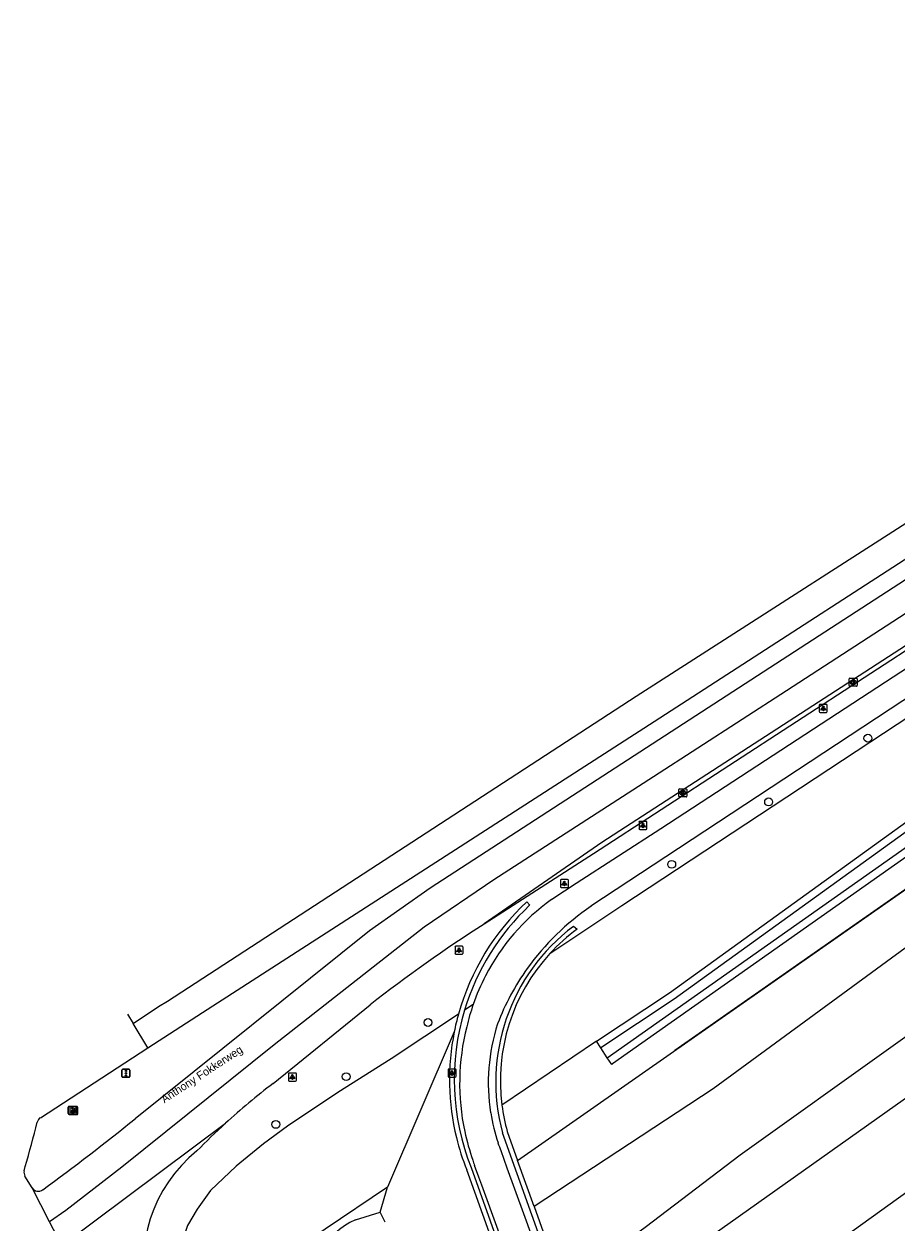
# Model space of a CAD drawing. Extents: x 156502 to 159074, y 384229 to 386094.
# Drawn here: x 156577.6 to 156686.5, y 385670.7 to 385820.5 of the extents above; entities that cross this region are included whole.
import ezdxf

# ---------------------------------------------------------------- set-up
doc = ezdxf.new("R2010")
doc.units = 0
for name, color, linetype in [('IMGEO_Berm_groen', 7, 'Continuous'), ('IMGEO_Boom', 7, 'Continuous'), ('IMGEO_Fietspad_gesloten', 7, 'Continuous'), ('IMGEO_Groenvoorziening', 7, 'Continuous'), ('IMGEO_Haag', 7, 'Continuous'), ('IMGEO_Hek', 7, 'Continuous'), ('IMGEO_Kolk', 7, 'Continuous'), ('IMGEO_Lichtpunt', 7, 'Continuous'), ('IMGEO_Loofbos', 7, 'Continuous'), ('IMGEO_Openbare_ruimte_label', 7, 'Continuous'), ('IMGEO_Rijbaan_regionaal_gesloten', 7, 'Continuous'), ('IMGEO_Rijbaan_regionaal_open', 7, 'Continuous'), ('IMGEO_Verkeersregelinstallatiepaal', 7, 'Continuous'), ('IMGEO_Waterloop', 7, 'Continuous')]:
    doc.layers.add(name, color=color, linetype=linetype)

msp = doc.modelspace()

# ---------------------------------------------------------------- linework, layer by layer
at = {"layer": 'IMGEO_Berm_groen'}
for points in [[(156633.7, 385697.92), (156632.64, 385697.21)], [(156631.87, 385696.71), (156623.47, 385691.12), (156616.78, 385686.91), (156610.49, 385682.74), (156607.53, 385680.53), (156604.1, 385677.72), (156600.9, 385674.67), (156599.21, 385672.33), (156598, 385670.31), (156597.11, 385667.59), (156596.91, 385665.45), (156597.24, 385662.91), (156597.95, 385660.68), (156598.83, 385658.73), (156598.95, 385658.46)], [(156623.02, 385675.08), (156615.23, 385669.86), (156612.01, 385667.6), (156610.4, 385666.16), (156609.58, 385664.78), (156609.43, 385663.6)], [(156622.07, 385671.98), (156623.02, 385675.08)], [(156618.99, 385671.01), (156622.07, 385671.98)]]:
    msp.add_lwpolyline(points, dxfattribs=at)
msp.add_arc((156622.65, 385662.64), 9.14, 113.6111, 190.3391, dxfattribs=at)
at = {"layer": 'IMGEO_Boom'}
for centre in [(156683.03, 385731.21), (156670.62, 385723.25), (156658.52, 385715.44), (156628.07, 385695.68), (156617.84, 385688.91), (156609.05, 385682.94)]:
    msp.add_circle(centre, 0.489, dxfattribs=at)
at = {"layer": 'IMGEO_Fietspad_gesloten'}
for points in [[(156643.48, 385711.04), (156643.67, 385711.17), (156646.56, 385713.1), (156657.17, 385719.91), (156703.21, 385750), (156750.52, 385780.64)], [(156753.13, 385778.55), (156708.86, 385750), (156659.36, 385717.42), (156648.43, 385710.2)], [(156637.15, 385679.66), (156637.93, 385677.52), (156639.99, 385671.81), (156643.65, 385661.67), (156655.22, 385629.6), (156675.23, 385574.61), (156675.33, 385574.38)], [(156670.43, 385577.01), (156651.82, 385628.48), (156640.76, 385658.91), (156636.83, 385669.74), (156634.8, 385675.33), (156634.43, 385676.33), (156633.89, 385677.82)]]:
    msp.add_lwpolyline(points, dxfattribs=at)
for centre, radius, start, end in [((156659.26, 385689.08), 27.04, 125.7042, 152.5869), ((156665.86, 385684.39), 31.14, 124.0201, 144.6192), ((156665.84, 385684.38), 31.14, 144.5922, 159.0539), ((156659.62, 385688.91), 27.44, 152.6203, 160.8293), ((156659.3, 385689.07), 27.08, 160.914, 167.0597), ((156661.01, 385688.06), 28.99, 165.8665, 191.9715), ((156659.35, 385688.13), 23.76, 161.9028, 189.0873), ((156659.3, 385688.12), 23.7, 189.0889, 198.4368), ((156661.06, 385688.07), 29.03, 191.9838, 199.2948), ((156658.73, 385687.92), 23.1, 198.4016, 200.9437), ((156670.1, 385691.36), 38.66, 199.472, 200.5082)]:
    msp.add_arc(centre, radius, start, end, dxfattribs=at)
at = {"layer": 'IMGEO_Groenvoorziening'}
for points in [[(156649.11, 385693.35), (156658.26, 385699.4), (156728.34, 385750), (156739.88, 385758.41)], [(156631.35, 385694.52), (156623.02, 385675.08)], [(156622.72, 385670.71), (156622.07, 385671.98)]]:
    msp.add_lwpolyline(points, dxfattribs=at)
at = {"layer": 'IMGEO_Haag'}
for points in [[(156640.42, 385710.77), (156640.77, 385710.34)], [(156646.23, 385707.7), (156646.71, 385707.36)], [(156679.06, 385548.23), (156671.92, 385544.5), (156671.64, 385545.03), (156684.61, 385551.78), (156682.52, 385556.79), (156677.05, 385561.67), (156677.06, 385570.89), (156637.37, 385681.88)], [(156637.97, 385682.04), (156639.26, 385678.45)], [(156641.32, 385672.69), (156639.26, 385678.45)], [(156669.96, 385574.02), (156650.07, 385629.36), (156632.9, 385677.28)], [(156633.45, 385677.54), (156650.55, 385629.62), (156670.51, 385574.18)], [(156641.32, 385672.69), (156644.93, 385662.6)]]:
    msp.add_lwpolyline(points, dxfattribs=at)
for centre, radius, start, end in [((156661.18, 385688.51), 30.44, 133.0101, 164.3829), ((156661.29, 385688.54), 29.94, 133.2726, 163.1579), ((156660.88, 385688.24), 24.35, 126.9671, 195.1395), ((156660.6, 385688.44), 23.47, 126.2616, 137.4903), ((156660.64, 385688.39), 23.54, 137.4697, 187.3932), ((156661.28, 385688.54), 29.93, 163.1451, 201.5634), ((156660.95, 385688.58), 30.2, 164.377, 168.6493), ((156661.19, 385688.51), 30.44, 168.6215, 193.7176), ((156660.71, 385688.4), 23.61, 187.3968, 195.6149), ((156661.19, 385688.51), 30.44, 193.716, 201.6479)]:
    msp.add_arc(centre, radius, start, end, dxfattribs=at)
at = {"layer": 'IMGEO_Hek'}
msp.add_lwpolyline([(156741.65, 385750), (156658.92, 385692.19)], dxfattribs=at)
at = {"layer": 'IMGEO_Kolk'}
for p, q in [((156680.68, 385737.78), (156680.68, 385738.63)), ((156680.76, 385738.7), (156681.61, 385738.7)), ((156681.17, 385738.48), (156681.19, 385738.48)), ((156681.68, 385738.63), (156681.68, 385737.78)), ((156681.61, 385737.7), (156680.76, 385737.7)), ((156681.19, 385737.92), (156681.17, 385737.92)), ((156659.48, 385724.88), (156660.33, 385724.88)), ((156659.41, 385723.95), (156659.41, 385724.81)), ((156660.33, 385723.88), (156659.48, 385723.88)), ((156659.89, 385724.66), (156659.92, 385724.66)), ((156659.92, 385724.1), (156659.89, 385724.1)), ((156660.41, 385724.81), (156660.41, 385723.95))]:
    msp.add_line(p, q, dxfattribs=at)
for points in [[(156680.68, 385737.78), (156680.68, 385738.63)], [(156680.76, 385738.7), (156681.61, 385738.7)], [(156681, 385738.4), (156681.13, 385738.4), (156681.13, 385738.25), (156681.25, 385738.4), (156681.42, 385738.4), (156681.27, 385738.25), (156681.43, 385738), (156681.27, 385738), (156681.19, 385738.17), (156681.13, 385738.1), (156681.13, 385738), (156681, 385738), (156681, 385738.4)], [(156681.68, 385738.63), (156681.68, 385737.78)], [(156681.61, 385737.7), (156680.76, 385737.7)], [(156659.48, 385724.88), (156660.33, 385724.88)], [(156659.41, 385723.95), (156659.41, 385724.81)], [(156660.33, 385723.88), (156659.48, 385723.88)], [(156659.73, 385724.58), (156659.85, 385724.58), (156659.85, 385724.43), (156659.98, 385724.58), (156660.14, 385724.58), (156660, 385724.43), (156660.15, 385724.18), (156660, 385724.18), (156659.91, 385724.34), (156659.85, 385724.28), (156659.85, 385724.18), (156659.73, 385724.18), (156659.73, 385724.58)], [(156660.41, 385724.81), (156660.41, 385723.95)]]:
    msp.add_lwpolyline(points, dxfattribs=at)
for centre, start, end in [((156680.76, 385738.63), 91.552, 178.448), ((156680.76, 385738.63), 91.552, 178.448), ((156681.61, 385738.63), 1.552, 88.448), ((156681.61, 385738.63), 1.552, 88.448), ((156680.76, 385737.78), 181.552, 268.448), ((156680.76, 385737.78), 181.552, 268.448), ((156681.61, 385737.78), 271.552, 358.448), ((156681.61, 385737.78), 271.552, 358.448), ((156659.48, 385724.8), 91.552, 178.448), ((156659.48, 385724.8), 91.552, 178.448), ((156660.33, 385724.8), 1.552, 88.448), ((156660.33, 385724.8), 1.552, 88.448), ((156659.48, 385723.95), 181.552, 268.448), ((156659.48, 385723.95), 181.552, 268.448), ((156660.33, 385723.95), 271.552, 358.448), ((156660.33, 385723.95), 271.552, 358.448)]:
    msp.add_arc(centre, 0.0765, start, end, dxfattribs=at)
for centre, major_axis, ratio, start_param, end_param in [((156681.17, 385738.2), (-0.387, 0.002), 0.722429, 4.712389, 7.853982), ((156681.19, 385738.2), (-0.39, 0.002), 0.717154, 1.570796, 4.712389), ((156659.89, 385724.38), (-0.387, 0.002), 0.722429, 4.712389, 7.853982), ((156659.92, 385724.38), (-0.39, 0.002), 0.717154, 1.570796, 4.712389)]:
    msp.add_ellipse(centre, major_axis=major_axis, ratio=ratio, start_param=start_param, end_param=end_param, dxfattribs=at)
at = {"layer": 'IMGEO_Lichtpunt'}
for p, q in [((156676.95, 385735.35), (156676.95, 385734.54)), ((156676.95, 385735.35), (156676.95, 385734.54)), ((156677.85, 385735.44), (156677.05, 385735.44)), ((156677.85, 385735.44), (156677.05, 385735.44)), ((156677.95, 385734.54), (156677.95, 385735.35)), ((156677.95, 385734.54), (156677.95, 385735.35)), ((156677.05, 385734.44), (156677.85, 385734.44)), ((156677.05, 385734.44), (156677.85, 385734.44)), ((156654.43, 385720.72), (156654.43, 385719.92)), ((156654.43, 385720.72), (156654.43, 385719.92)), ((156655.33, 385720.82), (156654.52, 385720.82)), ((156655.33, 385720.82), (156654.52, 385720.82)), ((156655.42, 385719.92), (156655.42, 385720.72)), ((156655.42, 385719.92), (156655.42, 385720.72)), ((156654.52, 385719.82), (156655.33, 385719.82)), ((156654.52, 385719.82), (156655.33, 385719.82)), ((156644.61, 385713.45), (156644.61, 385712.65)), ((156644.61, 385713.45), (156644.61, 385712.65)), ((156645.51, 385713.55), (156644.7, 385713.55)), ((156645.51, 385713.55), (156644.7, 385713.55)), ((156645.6, 385712.65), (156645.6, 385713.45)), ((156645.6, 385712.65), (156645.6, 385713.45)), ((156644.7, 385712.55), (156645.51, 385712.55)), ((156644.7, 385712.55), (156645.51, 385712.55)), ((156631.44, 385705.12), (156631.44, 385704.32)), ((156631.44, 385705.12), (156631.44, 385704.32)), ((156632.34, 385705.22), (156631.53, 385705.22)), ((156632.34, 385705.22), (156631.53, 385705.22)), ((156631.53, 385704.22), (156632.34, 385704.22)), ((156631.53, 385704.22), (156632.34, 385704.22)), ((156632.44, 385704.32), (156632.44, 385705.12)), ((156632.44, 385704.32), (156632.44, 385705.12)), ((156610.62, 385689.26), (156610.62, 385688.45)), ((156610.62, 385689.26), (156610.62, 385688.45)), ((156611.52, 385689.36), (156610.72, 385689.36)), ((156611.52, 385689.36), (156610.72, 385689.36)), ((156611.62, 385688.45), (156611.62, 385689.26)), ((156611.62, 385688.45), (156611.62, 385689.26)), ((156630.57, 385689.76), (156630.57, 385688.96)), ((156630.57, 385689.76), (156630.57, 385688.96)), ((156631.47, 385689.86), (156630.67, 385689.86)), ((156631.47, 385689.86), (156630.67, 385689.86)), ((156631.57, 385688.96), (156631.57, 385689.76)), ((156631.57, 385688.96), (156631.57, 385689.76)), ((156610.72, 385688.36), (156611.52, 385688.36)), ((156610.72, 385688.36), (156611.52, 385688.36)), ((156630.67, 385688.86), (156631.47, 385688.86)), ((156630.67, 385688.86), (156631.47, 385688.86)), ((156583.31, 385685.07), (156583.31, 385684.26)), ((156583.31, 385685.07), (156583.31, 385684.26)), ((156584.21, 385685.16), (156583.41, 385685.16)), ((156584.21, 385685.16), (156583.41, 385685.16)), ((156584.31, 385684.26), (156584.31, 385685.07)), ((156584.31, 385684.26), (156584.31, 385685.07)), ((156583.41, 385684.17), (156584.21, 385684.17)), ((156583.41, 385684.17), (156584.21, 385684.17))]:
    msp.add_line(p, q, dxfattribs=at)
for points in [[(156677.33, 385735.01), (156677.37, 385734.98), (156677.18, 385734.72), (156677.14, 385734.75), (156677.33, 385735.01)], [(156677.43, 385734.96), (156677.48, 385734.96), (156677.48, 385734.64), (156677.43, 385734.64), (156677.43, 385734.96)], [(156677.54, 385734.98), (156677.58, 385735.01), (156677.76, 385734.75), (156677.73, 385734.72), (156677.54, 385734.98)], [(156654.8, 385720.39), (156654.84, 385720.36), (156654.65, 385720.1), (156654.61, 385720.12), (156654.8, 385720.39)], [(156655.01, 385720.36), (156655.05, 385720.39), (156655.24, 385720.12), (156655.2, 385720.1), (156655.01, 385720.36)], [(156654.9, 385720.34), (156654.95, 385720.34), (156654.95, 385720.02), (156654.9, 385720.02), (156654.9, 385720.34)], [(156644.98, 385713.12), (156645.02, 385713.09), (156644.83, 385712.83), (156644.79, 385712.86), (156644.98, 385713.12)], [(156645.08, 385713.07), (156645.13, 385713.07), (156645.13, 385712.75), (156645.08, 385712.75), (156645.08, 385713.07)], [(156645.19, 385713.09), (156645.23, 385713.12), (156645.42, 385712.85), (156645.38, 385712.83), (156645.19, 385713.09)], [(156631.81, 385704.79), (156631.85, 385704.76), (156631.66, 385704.5), (156631.63, 385704.52), (156631.81, 385704.79)], [(156631.91, 385704.74), (156631.96, 385704.74), (156631.96, 385704.42), (156631.91, 385704.42), (156631.91, 385704.74)], [(156632.02, 385704.76), (156632.06, 385704.79), (156632.25, 385704.52), (156632.21, 385704.5), (156632.02, 385704.76)], [(156611, 385688.92), (156611.03, 385688.9), (156610.85, 385688.63), (156610.81, 385688.66), (156611, 385688.92)], [(156611.21, 385688.9), (156611.25, 385688.92), (156611.43, 385688.66), (156611.39, 385688.63), (156611.21, 385688.9)], [(156630.95, 385689.43), (156630.98, 385689.4), (156630.8, 385689.14), (156630.76, 385689.16), (156630.95, 385689.43)], [(156631.05, 385689.38), (156631.1, 385689.38), (156631.1, 385689.06), (156631.05, 385689.06), (156631.05, 385689.38)], [(156631.16, 385689.4), (156631.2, 385689.43), (156631.38, 385689.16), (156631.34, 385689.14), (156631.16, 385689.4)], [(156611.1, 385688.88), (156611.15, 385688.88), (156611.15, 385688.55), (156611.1, 385688.55), (156611.1, 385688.88)], [(156583.69, 385684.73), (156583.72, 385684.7), (156583.54, 385684.44), (156583.5, 385684.47), (156583.69, 385684.73)], [(156583.79, 385684.68), (156583.84, 385684.68), (156583.84, 385684.36), (156583.79, 385684.36), (156583.79, 385684.68)], [(156583.9, 385684.7), (156583.94, 385684.73), (156584.12, 385684.47), (156584.08, 385684.44), (156583.9, 385684.7)]]:
    msp.add_lwpolyline(points, dxfattribs=at)
for centre in [(156677.45, 385735.14), (156654.93, 385720.52), (156645.11, 385713.25), (156631.94, 385704.92), (156611.12, 385689.06), (156631.07, 385689.56), (156583.81, 385684.87)]:
    msp.add_circle(centre, 0.0994, dxfattribs=at)
for centre, start, end in [((156677.05, 385735.35), 90, 180), ((156677.05, 385735.35), 90, 180), ((156677.85, 385735.35), 0, 90), ((156677.85, 385735.35), 0, 90), ((156677.05, 385734.54), 180, 270), ((156677.05, 385734.54), 180, 270), ((156677.85, 385734.54), 270, 0), ((156677.85, 385734.54), 270, 360), ((156654.52, 385720.72), 90, 180), ((156654.52, 385720.72), 90, 180), ((156655.33, 385720.72), 0, 90), ((156655.33, 385720.72), 0, 90), ((156654.52, 385719.92), 180, 270), ((156654.52, 385719.92), 180, 270), ((156655.33, 385719.92), 270, 0), ((156655.33, 385719.92), 270, 360), ((156644.7, 385713.45), 90, 180), ((156644.7, 385713.45), 90, 180), ((156645.51, 385713.45), 0, 90), ((156645.51, 385713.45), 0, 90), ((156644.7, 385712.65), 180, 270), ((156644.7, 385712.65), 180, 270), ((156645.51, 385712.65), 270, 0), ((156645.51, 385712.65), 270, 360), ((156631.53, 385705.12), 90, 180), ((156631.53, 385705.12), 90, 180), ((156631.53, 385704.32), 180, 270), ((156631.53, 385704.32), 180, 270), ((156632.34, 385705.12), 0, 90), ((156632.34, 385705.12), 0, 90), ((156632.34, 385704.32), 270, 0), ((156632.34, 385704.32), 270, 360), ((156610.72, 385689.26), 90, 180), ((156610.72, 385689.26), 90, 180), ((156611.52, 385689.26), 0, 90), ((156611.52, 385689.26), 0, 90), ((156630.67, 385689.76), 90, 180), ((156630.67, 385689.76), 90, 180), ((156630.67, 385688.96), 180, 270), ((156630.67, 385688.96), 180, 270), ((156631.47, 385689.76), 0, 90), ((156631.47, 385689.76), 0, 90), ((156631.47, 385688.96), 270, 0), ((156631.47, 385688.96), 270, 360), ((156610.72, 385688.45), 180, 270), ((156610.72, 385688.45), 180, 270), ((156611.52, 385688.45), 270, 0), ((156611.52, 385688.45), 270, 360), ((156583.41, 385685.07), 90, 180), ((156583.41, 385685.07), 90, 180), ((156584.21, 385685.07), 0, 90), ((156584.21, 385685.07), 0, 90), ((156583.41, 385684.26), 180, 270), ((156583.41, 385684.26), 180, 270), ((156584.21, 385684.26), 270, 0), ((156584.21, 385684.26), 270, 360)]:
    msp.add_arc(centre, 0.0946, start, end, dxfattribs=at)
at = {"layer": 'IMGEO_Loofbos'}
for points in [[(156643.29, 385704.3), (156652.3, 385710.29), (156712.54, 385750), (156761.01, 385781.57), (156786.11, 385798.7), (156788.68, 385800.45), (156799.05, 385807.82)], [(156639.26, 385678.45), (156741.65, 385750), (156747.28, 385753.93)], [(156741.93, 385754.71), (156735.54, 385750), (156651.12, 385690.5), (156651.03, 385690.44), (156650.47, 385691.28)], [(156665.32, 385658.26), (156753.83, 385721.97), (156762.12, 385733.03), (156756.59, 385741.83), (156749.3, 385747.61), (156741.76, 385744.6), (156663.69, 385687.4), (156641.32, 385672.69)], [(156644.93, 385662.6), (156655.21, 385670.1), (156667.09, 385679.14), (156743.52, 385733.78), (156747.29, 385735.79), (156750.31, 385733.78), (156750.56, 385730.77), (156658.95, 385665.75), (156653.11, 385660.42), (156650.59, 385657.54), (156648.8, 385653.41), (156648.63, 385652.28)], [(156649.11, 385693.35), (156637.3, 385685.36)], [(156649.66, 385692.51), (156649.11, 385693.35)]]:
    msp.add_lwpolyline(points, dxfattribs=at)
at = {"layer": 'IMGEO_Rijbaan_regionaal_gesloten'}
for points in [[(156888.82, 385899.83), (156879.36, 385890.79), (156870.12, 385882), (156843.89, 385857.99), (156834.98, 385850.17), (156825.86, 385842.58), (156813.58, 385832.66), (156801.04, 385822.91), (156788.39, 385813.49), (156778.71, 385806.59), (156768.9, 385799.83), (156755.77, 385791), (156735.95, 385778.05), (156716.04, 385765.09), (156702.77, 385756.55), (156686.14, 385745.74), (156672.85, 385737.15), (156656.24, 385726.4), (156636.3, 385713.49), (156627.6, 385707.58), (156608.84, 385692.88), (156589.82, 385677.58), (156582.82, 385672.19), (156580.79, 385670.76)], [(156765.7, 385802.07), (156756.82, 385796.07), (156749.55, 385791.22), (156730.97, 385779.04), (156686.2, 385750), (156628.33, 385712.45), (156620.77, 385707.13), (156591.48, 385683.65)], [(156770.3, 385796.74), (156748.42, 385782.2), (156698.01, 385749.42), (156649.78, 385718.19), (156635.07, 385707.99)], [(156591.23, 385695.55), (156594.39, 385697.66), (156595.53, 385698.33), (156654.09, 385736.45), (156698.33, 385764.9), (156706.5, 385770.16), (156714.54, 385775.36), (156716.74, 385776.8), (156721.03, 385779.59), (156723.54, 385781.22), (156726.52, 385783.11), (156728.73, 385784.57), (156731.96, 385786.67), (156734.39, 385788.25), (156742.59, 385793.55), (156743.1, 385793.88)], [(156593.08, 385692.5), (156599.9, 385696.91), (156656.31, 385733.31), (156699.34, 385761.12), (156719.11, 385773.89), (156743.1, 385793.88)], [(156590.51, 385696.73), (156591.23, 385695.55)], [(156608.72, 385688.05), (156620.82, 385697.89)], [(156593.08, 385692.5), (156591.23, 385695.55)], [(156579.63, 385683.78), (156593.08, 385692.5)], [(156582.31, 385667.8), (156602.76, 385683.08)], [(156577.59, 385677.14), (156577.73, 385677.66)], [(156578.61, 385675.01), (156577.71, 385676.46)], [(156580.79, 385670.76), (156578.61, 385675.01)], [(156582.31, 385667.8), (156580.79, 385670.76)]]:
    msp.add_lwpolyline(points, dxfattribs=at)
for centre, radius, start, end in [((156739.38, 385545.74), 192.88, 122.7381, 127.9285), ((156660.51, 385619.86), 85.63, 127.2178, 132.4142), ((156453.66, 385714.24), 129.35, 343.5756, 346.1286), ((156580.25, 385682.94), 1.05, 126.4758, 164.2298), ((156386.1, 385938.96), 327.67, 306.2642, 308.8145), ((156660.35, 385619.98), 85.43, 132.3883, 135.7183), ((156610.56, 385665.58), 18.07, 128.9845, 195.2482), ((156578.74, 385676.99), 1.16, 172.3359, 207.1333), ((156579.38, 385675.49), 0.904, 211.6741, 306.2976)]:
    msp.add_arc(centre, radius, start, end, dxfattribs=at)
at = {"layer": 'IMGEO_Rijbaan_regionaal_open'}
msp.add_lwpolyline([(156635.07, 385707.99), (156648.73, 385716.81), (156699.49, 385749.8), (156749.15, 385782.17)], dxfattribs=at)
at = {"layer": 'IMGEO_Verkeersregelinstallatiepaal'}
for p, q in [((156589.83, 385688.93), (156589.83, 385689.73)), ((156589.83, 385689.73), (156589.83, 385688.93)), ((156589.93, 385689.83), (156590.71, 385689.83)), ((156590.71, 385689.83), (156589.93, 385689.83)), ((156590.81, 385689.73), (156590.81, 385688.93)), ((156590.81, 385688.93), (156590.81, 385689.73)), ((156590.71, 385688.83), (156589.93, 385688.83)), ((156589.93, 385688.83), (156590.71, 385688.83)), ((156583.12, 385684.29), (156583.12, 385685.09)), ((156583.12, 385685.09), (156583.12, 385684.29)), ((156583.22, 385685.19), (156584.01, 385685.19)), ((156584.01, 385685.19), (156583.22, 385685.19)), ((156584.11, 385685.09), (156584.11, 385684.29)), ((156584.11, 385684.29), (156584.11, 385685.09)), ((156584.01, 385684.19), (156583.22, 385684.19)), ((156583.22, 385684.19), (156584.01, 385684.19))]:
    msp.add_line(p, q, dxfattribs=at)
for centre in [(156590.32, 385689.62), (156590.32, 385689.33), (156590.32, 385689.04), (156583.61, 385684.98), (156583.61, 385684.69), (156583.61, 385684.4)]:
    msp.add_circle(centre, 0.085, dxfattribs=at)
for centre, start, end in [((156589.93, 385689.73), 90, 180), ((156589.93, 385689.73), 90, 180), ((156589.93, 385688.93), 180, 270), ((156589.93, 385688.93), 180, 270), ((156590.71, 385689.73), 0, 90), ((156590.71, 385689.73), 360, 90), ((156590.71, 385688.93), 270, 0), ((156590.71, 385688.93), 270, 0), ((156583.22, 385685.09), 90, 180), ((156583.22, 385685.09), 90, 180), ((156584.01, 385685.09), 0, 90), ((156584.01, 385685.09), 360, 90), ((156583.22, 385684.29), 180, 270), ((156583.22, 385684.29), 180, 270), ((156584.01, 385684.29), 270, 0), ((156584.01, 385684.29), 270, 0)]:
    msp.add_arc(centre, 0.1, start, end, dxfattribs=at)
at = {"layer": 'IMGEO_Waterloop'}
for points in [[(156740.28, 385757.46), (156728.93, 385749.19), (156658.83, 385698.58), (156649.66, 385692.51)], [(156650.47, 385691.28), (156734.95, 385750.82), (156741.33, 385755.55)], [(156650.47, 385691.28), (156649.66, 385692.51)]]:
    msp.add_lwpolyline(points, dxfattribs=at)

# ---------------------------------------------------------------- texts
at = {"layer": 'IMGEO_Openbare_ruimte_label'}
msp.add_text('Anthony Fokkerweg', height=1, rotation=33.1656, dxfattribs=at).set_placement((156595.13, 385685.57))

doc.saveas('drawing.dxf')
